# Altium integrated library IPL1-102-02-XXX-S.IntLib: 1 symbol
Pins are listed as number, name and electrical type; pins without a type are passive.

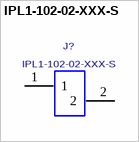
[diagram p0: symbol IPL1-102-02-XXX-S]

## IPL1-102-02-XXX-S
designator J?
.100[2.54] SINGLE ROW TERMINAL ASSEMBLY.; MANUFACTURER: SAMTEC
footprint IPL1-102-02-XXX-S
pins: 1, 2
